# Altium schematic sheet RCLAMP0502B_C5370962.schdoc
size 127 x 101 mm
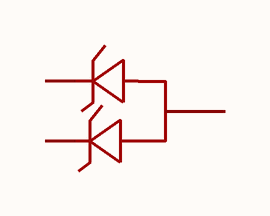
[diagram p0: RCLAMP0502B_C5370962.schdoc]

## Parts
D?  rclamp0502b_c5370962  [SOT-523_L1.6-W0.8-P1.00-LS1.6-BR]  (value not drawn)

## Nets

Not connected (* = marked no-connect by the designer): D? 1(C) 2(C) 3(A)

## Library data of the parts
D? = rclamp0502b_c5370962: 极性:单向;反向截止电压(Vrwm):5V;钳位电压:9V；15V;峰值脉冲电流(Ipp):4A@8/20us;峰值脉冲功率(Ppp):68W@8/20us;击穿电压:6.8V;; Manufacturer: TECH PUBLIC(台舟); AddInBom: yes; ModelId: 62a5eee6cc7e4598b9d48d5786c7bda6; ModelName: SOT-523_L1.6-W0.8-H0.2-P0.50-BL; ModelTransform: 62.992,62.992,0,270,0,0,0,0,0; Polarity: 单向; Reverse Stand-Off Voltage (Vrwm): 5V; Clamping Voltage: 9V；15V; Voltage - Breakdown: 6.8V; Reverse Leakage Current (Ir): 200nA; Number of Channels: 双路; level of protection: IEC 61000-4-2；IEC 61000-4-5; Type: ESD; Junction Capacitance: 0.5pF；0.35pF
